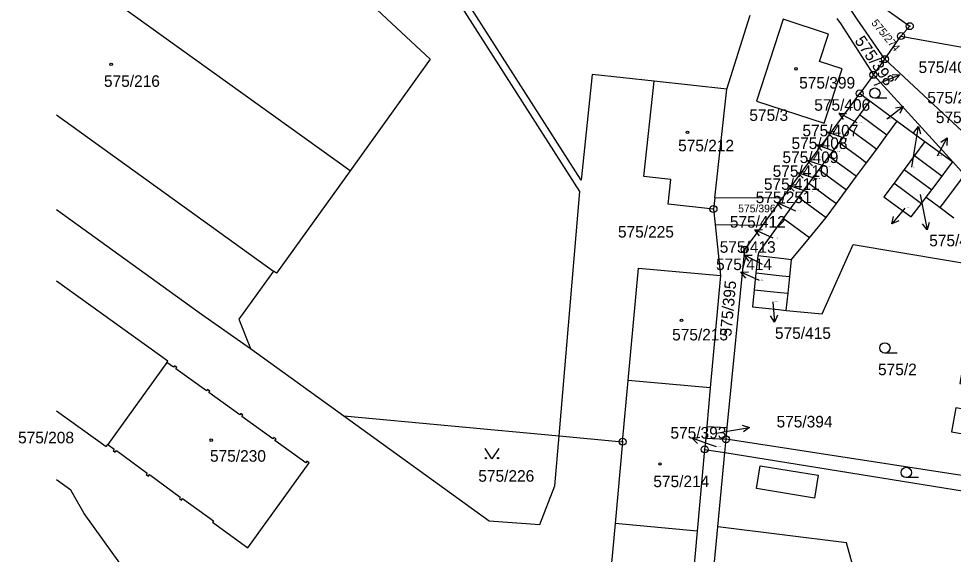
# Model space of a CAD drawing. Extents: x -737240 to -735272, y -1119606 to -1117878.
# Drawn here: x -737238.9 to -737101.6, y -1118864.9 to -1118786.2 of the extents above; entities that cross this region are included whole.
import ezdxf

# ---------------------------------------------------------------- set-up
doc = ezdxf.new("R2010")
doc.units = 0
for name, color, linetype in [('Level 1', 7, 'Continuous'), ('Level 16', 7, 'Continuous'), ('Level 18', 7, 'Continuous'), ('Level 19', 7, 'Continuous'), ('Level 25', 7, 'Continuous'), ('Level 4', 7, 'Continuous')]:
    doc.layers.add(name, color=color, linetype=linetype)

msp = doc.modelspace()

# ---------------------------------------------------------------- linework, layer by layer
at = {"layer": 'Level 1'}
for p, q in [((-737134.84, -1118796.58), (-737131.42, -1118785.69)), ((-737111.6, -1118792.15), (-737109.25, -1118788.75)), ((-737113.3, -1118794.45), (-737115.31, -1118797.19)), ((-737101.64, -1118807.25), (-737113.3, -1118794.45)), ((-737134.84, -1118796.58), (-737145.49, -1118795.4)), ((-737136.61, -1118812.52), (-737134.84, -1118796.58)), ((-737126.63, -1118812.57), (-737115.31, -1118797.19)), ((-737115.31, -1118797.19), (-737113.83, -1118798.28)), ((-737113.83, -1118798.28), (-737115.36, -1118800.35)), ((-737113.83, -1118798.28), (-737109.79, -1118801.25)), ((-737115.36, -1118800.35), (-737116.86, -1118802.38)), ((-737111.32, -1118803.32), (-737115.36, -1118800.35)), ((-737111.32, -1118803.32), (-737109.79, -1118801.25)), ((-737109.79, -1118801.25), (-737105.72, -1118804.24)), ((-737116.86, -1118802.38), (-737118.34, -1118804.39)), ((-737118.34, -1118804.39), (-737119.82, -1118806.39)), ((-737112.81, -1118805.36), (-737111.32, -1118803.32)), ((-737105.72, -1118804.24), (-737107.26, -1118806.32)), ((-737105.72, -1118804.24), (-737101.64, -1118807.25)), ((-737114.29, -1118807.37), (-737112.81, -1118805.36)), ((-737119.82, -1118806.39), (-737121.31, -1118808.39)), ((-737107.26, -1118806.32), (-737108.76, -1118808.36)), ((-737107.26, -1118806.32), (-737103.2, -1118809.33)), ((-737099.9, -1118809.16), (-737101.64, -1118807.25)), ((-737121.31, -1118808.39), (-737122.78, -1118810.39)), ((-737115.77, -1118809.37), (-737114.29, -1118807.37)), ((-737108.76, -1118808.36), (-737110.25, -1118810.36)), ((-737117.24, -1118811.38), (-737115.77, -1118809.37)), ((-737104.73, -1118811.36), (-737103.2, -1118809.33)), ((-737122.78, -1118810.39), (-737124.29, -1118812.43)), ((-737118.72, -1118813.39), (-737117.24, -1118811.38)), ((-737136.61, -1118812.52), (-737136.8, -1118814.19)), ((-737126.63, -1118812.57), (-737136.61, -1118812.52)), ((-737129.56, -1118816.56), (-737126.63, -1118812.57)), ((-737124.29, -1118812.43), (-737126.57, -1118815.58)), ((-737106.23, -1118813.35), (-737105.55, -1118812.45)), ((-737105.55, -1118812.45), (-737103.49, -1118813.97)), ((-737120.22, -1118815.43), (-737118.72, -1118813.39)), ((-737103.49, -1118813.97), (-737101.47, -1118815.46)), ((-737136.8, -1118814.19), (-737136.56, -1118816.47)), ((-737122.7, -1118818.43), (-737120.22, -1118815.43)), ((-737136.56, -1118816.47), (-737135.76, -1118823.96)), ((-737136.56, -1118816.47), (-737129.56, -1118816.56)), ((-737122.7, -1118818.43), (-737126.57, -1118815.58)), ((-737125.31, -1118821.58), (-737122.7, -1118818.43)), ((-737130.28, -1118821.02), (-737130.55, -1118823.56)), ((-737125.58, -1118824.11), (-737125.31, -1118821.58)), ((-737130.55, -1118823.56), (-737130.81, -1118826.04)), ((-737135.76, -1118823.96), (-737137.27, -1118840.49)), ((-737125.84, -1118826.57), (-737125.58, -1118824.11)), ((-737126.1, -1118829.08), (-737125.84, -1118826.57)), ((-737204.81, -1118834.71), (-737191.13, -1118844.58)), ((-737217.11, -1118836.73), (-737225.8, -1118848.8)), ((-737150.14, -1118848.4), (-737149.32, -1118839.39)), ((-737137.27, -1118840.49), (-737149.32, -1118839.39)), ((-737137.27, -1118840.49), (-737137.78, -1118846.13)), ((-737191.13, -1118844.58), (-737159.46, -1118847.53)), ((-737137.78, -1118846.13), (-737137.94, -1118847.87)), ((-737137.78, -1118846.13), (-737134.78, -1118846.31)), ((-737134.95, -1118848.03), (-737134.78, -1118846.31)), ((-737159.46, -1118847.53), (-737150.14, -1118848.4)), ((-737150.14, -1118848.4), (-737151.24, -1118860.43)), ((-737137.94, -1118847.87), (-737138.09, -1118849.52)), ((-737137.94, -1118847.87), (-737134.95, -1118848.03)), ((-737135.14, -1118849.99), (-737134.95, -1118848.03)), ((-737082.45, -1118856.09), (-737134.95, -1118848.03)), ((-737138.09, -1118849.52), (-737139.19, -1118861.53)), ((-737138.09, -1118849.52), (-737135.14, -1118849.99)), ((-737136.16, -1118860.88), (-737135.14, -1118849.99)), ((-737135.14, -1118849.99), (-737083.64, -1118858.26)), ((-737139.19, -1118861.53), (-737151.24, -1118860.43)), ((-737139.19, -1118861.53), (-737140.36, -1118874.39)), ((-737137.46, -1118874.72), (-737136.16, -1118860.88))]:
    msp.add_line(p, q, dxfattribs=at)
for points in [[(-737145.49, -1118795.4), (-737154.6, -1118794.38), (-737156.25, -1118809.94), (-737196.63, -1118746.68), (-737199.36, -1118744.91)], [(-737159.46, -1118847.53), (-737156.43, -1118811.62), (-737197.51, -1118747.24), (-737199.88, -1118745.73)], [(-737208.49, -1118759.28), (-737210.42, -1118762.32), (-737178.42, -1118792.14), (-737190.17, -1118808.55)], [(-737190.17, -1118808.55), (-737233.313, -1118777.523)], [(-737114.01, -1118782.94), (-737107.95, -1118787.3), (-737109.25, -1118788.75)], [(-737111.6, -1118792.15), (-737115.67, -1118786.26), (-737116.67, -1118784.81)], [(-737119.89, -1118788.47), (-737126.55, -1118786.29), (-737130.49, -1118798.32), (-737120.51, -1118801.58), (-737117.87, -1118793.56), (-737121.21, -1118792.47), (-737119.89, -1118788.47)], [(-737118.66, -1118786.15), (-737118.15, -1118786.93), (-737113.3, -1118794.45)], [(-737109.25, -1118788.75), (-737087.65, -1118792.63), (-737072.62, -1118798.26)], [(-737113.3, -1118794.45), (-737112.6, -1118793.5), (-737111.6, -1118792.15)], [(-737084.58, -1118815.18), (-737091.7, -1118810.73), (-737111.6, -1118792.15)], [(-737136.8, -1118814.19), (-737143.45, -1118813.45), (-737143.05, -1118809.85), (-737147.05, -1118809.41), (-737145.49, -1118795.4)], [(-737233.313, -1118800.337), (-737201.42, -1118823.32)], [(-737116.86, -1118802.38), (-737113.75, -1118804.67), (-737112.81, -1118805.36)], [(-737118.34, -1118804.39), (-737115.24, -1118806.67), (-737114.29, -1118807.37)], [(-737119.82, -1118806.39), (-737116.72, -1118808.68), (-737115.77, -1118809.37)], [(-737103.2, -1118809.33), (-737102.55, -1118808.46), (-737101.64, -1118807.25)], [(-737190.17, -1118808.55), (-737201.01, -1118823.62), (-737201.42, -1118823.32)], [(-737121.31, -1118808.39), (-737118.2, -1118810.68), (-737117.24, -1118811.38)], [(-737108.76, -1118808.36), (-737107.85, -1118809.04), (-737104.73, -1118811.36)], [(-737103.49, -1118813.97), (-737102.81, -1118813.06), (-737100.5, -1118809.97), (-737099.9, -1118809.16)], [(-737122.78, -1118810.39), (-737119.68, -1118812.68), (-737118.72, -1118813.39)], [(-737110.25, -1118810.36), (-737111.75, -1118812.39), (-737110.85, -1118813.05), (-737107.73, -1118815.35), (-737106.23, -1118813.35)], [(-737110.25, -1118810.36), (-737109.34, -1118811.04), (-737106.23, -1118813.35)], [(-737105.55, -1118812.45), (-737104.87, -1118811.54), (-737104.73, -1118811.36)], [(-737124.29, -1118812.43), (-737121.19, -1118814.72), (-737120.22, -1118815.43)], [(-737233.313, -1118814.273), (-737212, -1118829.62), (-737204.81, -1118834.71)], [(-737134.78, -1118846.31), (-737132.2, -1118820.15), (-737129.56, -1118816.56)], [(-737126.57, -1118815.58), (-737130.15, -1118820.53), (-737130.28, -1118821.02)], [(-737126.1, -1118829.08), (-737120.84, -1118829.59), (-737116.29, -1118819.41), (-737088.82, -1118824), (-737081.92, -1118826.27), (-737072.73, -1118832.79), (-737070.71, -1118834.6)], [(-737130.28, -1118821.02), (-737126.45, -1118821.45), (-737125.31, -1118821.58)], [(-737201.42, -1118823.32), (-737206.51, -1118830.39), (-737204.81, -1118834.71)], [(-737149.32, -1118839.39), (-737147.81, -1118822.86), (-737135.76, -1118823.96)], [(-737130.55, -1118823.56), (-737126.71, -1118823.98), (-737125.58, -1118824.11)], [(-737217.11, -1118836.73), (-737216.98, -1118836.55), (-737233.313, -1118824.783)], [(-737130.81, -1118826.04), (-737131.07, -1118828.56), (-737127.22, -1118828.96), (-737126.1, -1118829.08)], [(-737130.81, -1118826.04), (-737126.96, -1118826.45), (-737125.84, -1118826.57)], [(-737087.87, -1118849.34), (-737084.35, -1118827.43), (-737095.48, -1118825.65), (-737095.53, -1118825.94), (-737098.09, -1118825.47), (-737098.7, -1118829.03), (-737096.09, -1118829.47), (-737097.26, -1118836.74), (-737099.97, -1118836.27), (-737100.58, -1118839.84), (-737097.83, -1118840.29), (-737098.41, -1118843.89), (-737101.2, -1118843.4), (-737101.81, -1118846.96), (-737098.98, -1118847.44), (-737099, -1118847.56)], [(-737225.8, -1118848.8), (-737224.84, -1118849.49), (-737224.99, -1118849.7), (-737224.68, -1118849.93), (-737224.52, -1118849.69), (-737219.99, -1118853), (-737220.14, -1118853.22), (-737219.83, -1118853.45), (-737219.67, -1118853.22), (-737215.13, -1118856.52), (-737215.27, -1118856.73), (-737214.96, -1118856.96), (-737214.81, -1118856.73), (-737210.26, -1118860.02), (-737210.42, -1118860.23), (-737205.23, -1118863.97), (-737196.21, -1118851.49), (-737196.53, -1118851.26), (-737196.68, -1118851.47), (-737201.22, -1118848.19), (-737201.07, -1118847.98), (-737201.39, -1118847.75), (-737201.54, -1118847.96), (-737206.09, -1118844.68), (-737205.93, -1118844.47), (-737206.25, -1118844.23), (-737206.41, -1118844.44), (-737210.95, -1118841.16), (-737210.81, -1118840.96), (-737211.13, -1118840.73), (-737211.28, -1118840.92), (-737215.81, -1118837.68), (-737215.65, -1118837.46), (-737215.97, -1118837.23), (-737216.13, -1118837.43), (-737217.11, -1118836.73)], [(-737233.313, -1118843.855), (-737226.02, -1118849.1), (-737225.8, -1118848.8)], [(-737191.13, -1118844.58), (-737169.75, -1118860), (-737162.33, -1118860.55), (-737160.08, -1118854.87), (-737159.46, -1118847.53)], [(-737233.313, -1118853.594), (-737233.31, -1118853.59), (-737233.313, -1118853.588)], [(-737222.63, -1118868.15), (-737229.28, -1118858.96), (-737231.21, -1118855.53), (-737233.313, -1118853.99)], [(-737151.24, -1118860.43), (-737152.39, -1118873.04), (-737153.32, -1118883.16), (-737141.26, -1118884.26), (-737140.36, -1118874.39)], [(-737085.32, -1118874.65), (-737105.47, -1118871.37), (-737116.1, -1118867.32), (-737117.24, -1118863.27), (-737136.16, -1118860.88)]]:
    msp.add_lwpolyline(points, dxfattribs=at)
at = {"layer": 'Level 16'}
for p, q in [((-737115.7, -1118801.5), (-737118.347, -1118800.088)), ((-737111.32, -1118800.94), (-737108.942, -1118799.111)), ((-737117.22, -1118803.89), (-737120.049, -1118802.892)), ((-737103.9, -1118806.36), (-737102.463, -1118803.726)), ((-737118.81, -1118805.76), (-737121.639, -1118804.762)), ((-737120.17, -1118807.99), (-737123.016, -1118807.041)), ((-737121.56, -1118809.79), (-737124.406, -1118808.841)), ((-737122.86, -1118811.69), (-737125.706, -1118810.741)), ((-737124.7, -1118814.52), (-737127.438, -1118813.294)), ((-737108.68, -1118814.04), (-737110.601, -1118816.345)), ((-737128, -1118818.48), (-737130.728, -1118817.233)), ((-737129.58, -1118822.36), (-737132.231, -1118820.956)), ((-737130.02, -1118824.69), (-737132.758, -1118823.463)), ((-737128.05, -1118827.83), (-737127.82, -1118830.821))]:
    msp.add_line(p, q, dxfattribs=at)
for points in [[(-737113.16, -1118795.99), (-737112.21, -1118795.6), (-737109.433, -1118794.465)], [(-737110.548, -1118794.381), (-737109.433, -1118794.465), (-737110.169, -1118795.306)], [(-737117.7, -1118801), (-737118.347, -1118800.088), (-737117.229, -1118800.118)], [(-737110.04, -1118799.324), (-737108.942, -1118799.111), (-737109.43, -1118800.117)], [(-737119.272, -1118803.696), (-737120.049, -1118802.892), (-737118.94, -1118802.753)], [(-737107.64, -1118808.03), (-737107.16, -1118805), (-737106.69, -1118802.037)], [(-737107.341, -1118802.946), (-737106.69, -1118802.037), (-737106.353, -1118803.103)], [(-737103.381, -1118804.365), (-737102.463, -1118803.726), (-737102.503, -1118804.844)], [(-737120.862, -1118805.566), (-737121.639, -1118804.762), (-737120.53, -1118804.623)], [(-737122.225, -1118807.832), (-737123.016, -1118807.041), (-737121.909, -1118806.883)], [(-737123.615, -1118809.632), (-737124.406, -1118808.841), (-737123.299, -1118808.683)], [(-737124.915, -1118811.532), (-737125.706, -1118810.741), (-737124.599, -1118810.583)], [(-737106.41, -1118812.06), (-737105.97, -1118814.28), (-737105.395, -1118817.224)], [(-737126.73, -1118814.159), (-737127.438, -1118813.294), (-737126.321, -1118813.246)], [(-737109.576, -1118815.897), (-737110.601, -1118816.345), (-737110.344, -1118815.256)], [(-737105.096, -1118816.147), (-737105.395, -1118817.224), (-737106.077, -1118816.339)], [(-737130.027, -1118818.103), (-737130.728, -1118817.233), (-737129.611, -1118817.194)], [(-737131.582, -1118821.866), (-737132.231, -1118820.956), (-737131.114, -1118820.982)], [(-737132.05, -1118824.328), (-737132.758, -1118823.463), (-737131.64, -1118823.416)], [(-737127.398, -1118829.786), (-737127.82, -1118830.821), (-737128.395, -1118829.862)], [(-737136.33, -1118847.14), (-737134.45, -1118846.81), (-737131.495, -1118846.29)], [(-737132.567, -1118845.971), (-737131.495, -1118846.29), (-737132.394, -1118846.956)], [(-737139.131, -1118848.675), (-737139.904, -1118847.867), (-737138.794, -1118847.734)], [(-737136.36, -1118849.14), (-737137.08, -1118848.88), (-737139.904, -1118847.867)]]:
    msp.add_lwpolyline(points, dxfattribs=at)
at = {"layer": 'Level 25'}
for p, q in [((-737111.298, -1118797.89), (-737113.08, -1118797.89)), ((-737109.828, -1118835.36), (-737111.61, -1118835.36)), ((-737106.678, -1118853.66), (-737108.46, -1118853.66))]:
    msp.add_line(p, q, dxfattribs=at)
msp.add_lwpolyline([(-737168.34, -1118849.39), (-737169.34, -1118850.89), (-737170.34, -1118849.39)], dxfattribs=at)
for centre in [(-737170.24, -1118850.79), (-737168.44, -1118850.79)]:
    msp.add_circle(centre, 0.1, dxfattribs=at)
for centre, major_axis, ratio in [((-737107.95, -1118787.3), (0.516, 0), 0.9848078), ((-737107.95, -1118787.3), (0.0375, 0), 0.9848078), ((-737109.25, -1118788.75), (0.516, 0), 0.9848078), ((-737109.25, -1118788.75), (0.0375, 0), 0.9848078), ((-737111.6, -1118792.15), (0.516, 0), 0.9848078), ((-737111.6, -1118792.15), (0.0375, 0), 0.9848078), ((-737225.29, -1118792.92), (0.18, 0), 0.9848078), ((-737124.67, -1118793.57), (0.18, 0), 0.9848078), ((-737113.3, -1118794.45), (0.516, 0), 0.9848078), ((-737113.3, -1118794.45), (0.0375, 0), 0.9848078), ((-737115.31, -1118797.19), (0.516, 0), 0.9848078), ((-737115.31, -1118797.19), (0.0375, 0), 0.9848078), ((-737113.08, -1118797.134), (0.764, 0), 0.9894236), ((-737140.61, -1118802.9), (0.18, 0), 0.9848078), ((-737136.8, -1118814.19), (0.516, 0), 0.9848078), ((-737136.8, -1118814.19), (0.0375, 0), 0.9848078), ((-737132.2, -1118820.15), (0.516, 0), 0.9848078), ((-737132.2, -1118820.15), (0.0375, 0), 0.9848078), ((-737141.49, -1118830.53), (0.18, 0), 0.9848078), ((-737111.61, -1118834.604), (0.764, 0), 0.9894236), ((-737210.59, -1118848.16), (0.18, 0), 0.9848078), ((-737150.14, -1118848.4), (0.516, 0), 0.9848078), ((-737150.14, -1118848.4), (0.0375, 0), 0.9848078), ((-737134.95, -1118848.03), (0.516, 0), 0.9848078), ((-737134.95, -1118848.03), (0.0375, 0), 0.9848078), ((-737138.09, -1118849.52), (0.516, 0), 0.9848078), ((-737138.09, -1118849.52), (0.0375, 0), 0.9848078), ((-737144.66, -1118851.66), (0.18, 0), 0.9848078), ((-737108.46, -1118852.904), (0.764, 0), 0.9894236)]:
    msp.add_ellipse(centre, major_axis=major_axis, ratio=ratio, dxfattribs=at)
at = {"layer": 'Level 4'}
msp.add_lwpolyline([(-737121.4, -1118853.32), (-737121.94, -1118856.67), (-737130.46, -1118855.29), (-737129.92, -1118851.94), (-737121.4, -1118853.32)], dxfattribs=at)

# ---------------------------------------------------------------- texts
at = {"layer": 'Level 16'}
for s, p in [('575/403', (-737106.66, -1118794.18)), ('575/250', (-737105.375, -1118798.66)), ('575/406', (-737121.985, -1118799.73)), ('575/417', (-737104.12, -1118801.55)), ('575/407', (-737123.725, -1118803.49)), ('575/408', (-737125.325, -1118805.36)), ('575/409', (-737126.655, -1118807.42)), ('575/410', (-737128.095, -1118809.45)), ('575/411', (-737129.385, -1118811.36)), ('575/251', (-737130.595, -1118813.31)), ('575/412', (-737134.385, -1118816.92)), ('575/418', (-737105.09, -1118819.66)), ('575/413', (-737135.875, -1118820.61)), ('575/414', (-737136.415, -1118823.16)), ('575/415', (-737127.76, -1118833.27)), ('575/394', (-737127.525, -1118846.29)), ('575/208', (-737238.97, -1118848.63)), ('575/393', (-737143.115, -1118847.93))]:
    msp.add_text(s, height=1.7, dxfattribs=at).set_placement(p)
at = {"layer": 'Level 18'}
for s, height, rotation, p in [('575/274', 1.14, 309.4101, (-737113.663, -1118786.871)), ('575/398', 1.7, 304.55289, (-737116.12, -1118789.46)), ('575/395', 1.7, 84.71457, (-737134.186, -1118832.968))]:
    msp.add_text(s, height=height, rotation=rotation, dxfattribs=at).set_placement(p)
for s, height, p in [('575/403', 0.1, (-737113.16, -1118795.99)), ('575/3', 1.7, (-737131.52, -1118801.23)), ('575/406', 0.1, (-737115.525, -1118801.5)), ('575/250', 0.1, (-737111.145, -1118800.94)), ('575/407', 0.1, (-737117.045, -1118803.89)), ('575/408', 0.1, (-737118.635, -1118805.76)), ('575/416', 0.1, (-737103.725, -1118806.36)), ('575/409', 0.1, (-737119.995, -1118807.99)), ('575/417', 0.1, (-737107.64, -1118808.03)), ('575/410', 0.1, (-737121.385, -1118809.79)), ('575/411', 0.1, (-737122.685, -1118811.69)), ('575/418', 0.1, (-737106.41, -1118812.06)), ('575/396', 1.14, (-737133.165, -1118814.67)), ('575/419', 0.1, (-737108.505, -1118814.04)), ('575/251', 0.1, (-737124.525, -1118814.52)), ('575/225', 1.7, (-737150.825, -1118818.38)), ('575/412', 0.1, (-737127.825, -1118818.48)), ('575/413', 0.1, (-737129.405, -1118822.36)), ('575/414', 0.1, (-737129.845, -1118824.69)), ('575/415', 0.1, (-737127.875, -1118827.83)), ('575/2', 1.7, (-737112.615, -1118838.61)), ('575/394', 0.1, (-737136.155, -1118847.14)), ('575/393', 0.1, (-737136.185, -1118849.14)), ('575/226', 1.7, (-737171.345, -1118854.27))]:
    msp.add_text(s, height=height, dxfattribs=at).set_placement(p)
at = {"layer": 'Level 19'}
for s, p in [('575/216', (-737226.35, -1118796.22)), ('575/399', (-737124.2, -1118796.47)), ('575/212', (-737141.99, -1118805.7)), ('575/213', (-737142.87, -1118833.5)), ('575/230', (-737210.77, -1118851.33)), ('575/214', (-737145.63, -1118855.07))]:
    msp.add_text(s, height=1.7, dxfattribs=at).set_placement(p)

doc.saveas('drawing.dxf')
